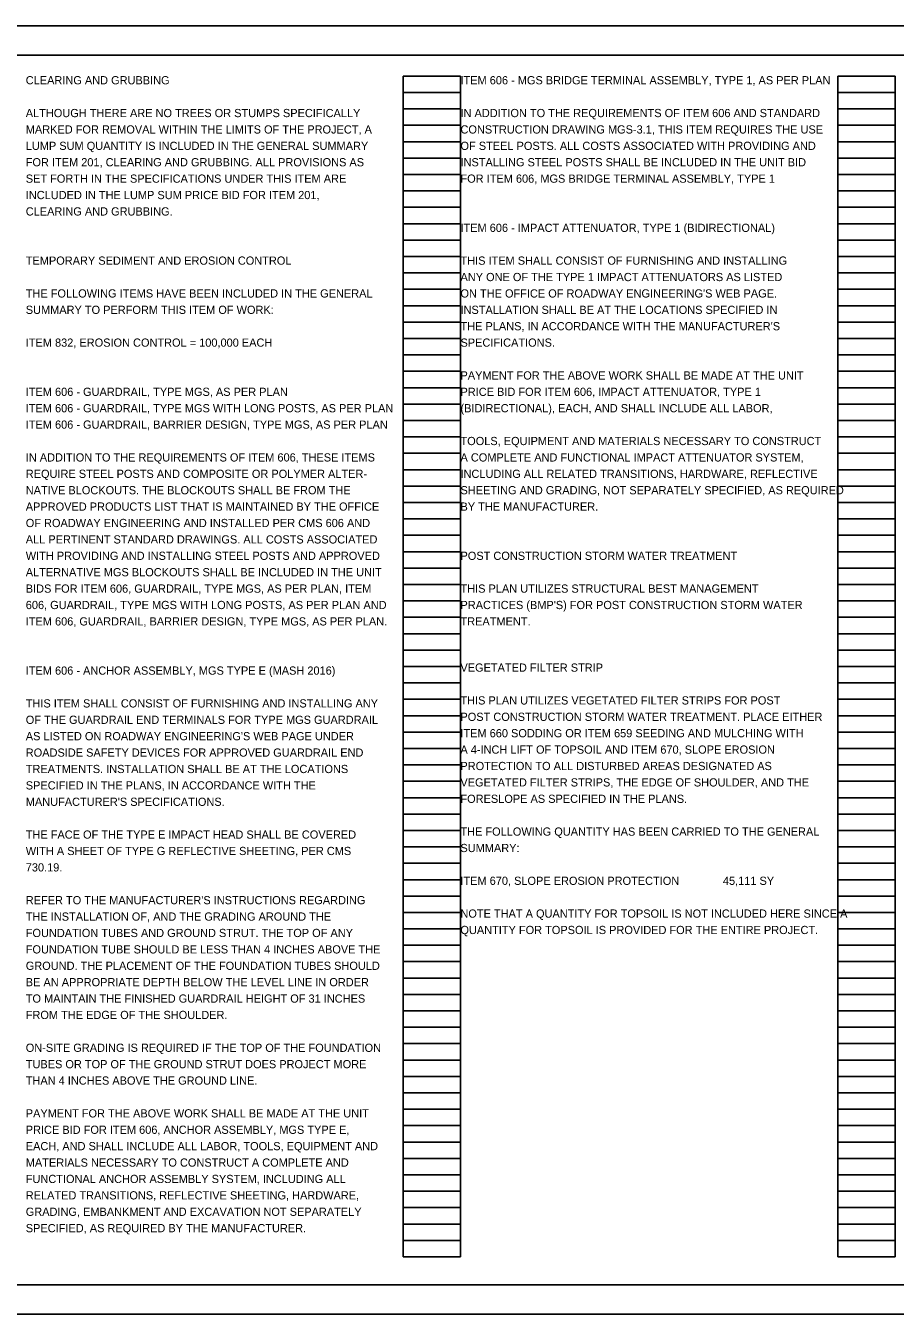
# Model space of a CAD drawing. Extents: x 0 to 46.1, y 0 to 22.
# Drawn here: x 9.82 to 24.66, y 0 to 22 of the extents above; entities that cross this region are included whole.
import ezdxf

# ---------------------------------------------------------------- set-up
doc = ezdxf.new("R2010")
doc.units = 0
for name, color, linetype in [('SH_Border', 7, 'Continuous'), ('SH_Cut_Line', 7, 'Continuous'), ('SH_Data', 7, 'Continuous'), ('SH_Text', 7, 'Continuous'), ('TX_P_Misc', 7, 'Continuous')]:
    doc.layers.add(name, color=color, linetype=linetype)

msp = doc.modelspace()

# ---------------------------------------------------------------- linework, layer by layer
at = {"layer": 'SH_Border'}
msp.add_lwpolyline([(1.5, 21.5), (33.5, 21.5), (33.5, 0.5), (1.5, 0.5)], close=True, dxfattribs=at)
at = {"layer": 'SH_Cut_Line'}
msp.add_lwpolyline([(0, 0), (34, 0), (34, 22), (0, 22)], close=True, dxfattribs=at)
at = {"layer": 'SH_Data'}
for p, q in [((16.26, 0.98), (16.26, 21.14)), ((16.26, 21.14), (17.24, 21.14)), ((17.24, 0.98), (17.24, 21.14)), ((23.68, 0.98), (23.68, 21.14)), ((23.68, 21.14), (24.66, 21.14)), ((24.66, 0.98), (24.66, 21.14)), ((16.26, 20.86), (17.24, 20.86)), ((23.68, 20.86), (24.66, 20.86)), ((16.26, 20.58), (17.24, 20.58)), ((23.68, 20.58), (24.66, 20.58)), ((16.26, 20.3), (17.24, 20.3)), ((23.68, 20.3), (24.66, 20.3)), ((16.26, 20.02), (17.24, 20.02)), ((23.68, 20.02), (24.66, 20.02)), ((16.26, 19.74), (17.24, 19.74)), ((23.68, 19.74), (24.66, 19.74)), ((16.26, 19.46), (17.24, 19.46)), ((23.68, 19.46), (24.66, 19.46)), ((16.26, 19.18), (17.24, 19.18)), ((23.68, 19.18), (24.66, 19.18)), ((16.26, 18.9), (17.24, 18.9)), ((23.68, 18.9), (24.66, 18.9)), ((16.26, 18.62), (17.24, 18.62)), ((23.68, 18.62), (24.66, 18.62)), ((16.26, 18.34), (17.24, 18.34)), ((23.68, 18.34), (24.66, 18.34)), ((16.26, 18.06), (17.24, 18.06)), ((23.68, 18.06), (24.66, 18.06)), ((16.26, 17.78), (17.24, 17.78)), ((23.68, 17.78), (24.66, 17.78)), ((16.26, 17.5), (17.24, 17.5)), ((23.68, 17.5), (24.66, 17.5)), ((16.26, 17.22), (17.24, 17.22)), ((23.68, 17.22), (24.66, 17.22)), ((16.26, 16.94), (17.24, 16.94)), ((23.68, 16.94), (24.66, 16.94)), ((16.26, 16.66), (17.24, 16.66)), ((23.68, 16.66), (24.66, 16.66)), ((16.26, 16.38), (17.24, 16.38)), ((23.68, 16.38), (24.66, 16.38)), ((16.26, 16.1), (17.24, 16.1)), ((23.68, 16.1), (24.66, 16.1)), ((16.26, 15.82), (17.24, 15.82)), ((23.68, 15.82), (24.66, 15.82)), ((16.26, 15.54), (17.24, 15.54)), ((23.68, 15.54), (24.66, 15.54)), ((16.26, 15.26), (17.24, 15.26)), ((23.68, 15.26), (24.66, 15.26)), ((16.26, 14.98), (17.24, 14.98)), ((23.68, 14.98), (24.66, 14.98)), ((16.26, 14.7), (17.24, 14.7)), ((23.68, 14.7), (24.66, 14.7)), ((16.26, 14.42), (17.24, 14.42)), ((23.68, 14.42), (24.66, 14.42)), ((16.26, 14.14), (17.24, 14.14)), ((23.68, 14.14), (24.66, 14.14)), ((16.26, 13.86), (17.24, 13.86)), ((23.68, 13.86), (24.66, 13.86)), ((16.26, 13.58), (17.24, 13.58)), ((23.68, 13.58), (24.66, 13.58)), ((16.26, 13.3), (17.24, 13.3)), ((23.68, 13.3), (24.66, 13.3)), ((16.26, 13.02), (17.24, 13.02)), ((23.68, 13.02), (24.66, 13.02)), ((16.26, 12.74), (17.24, 12.74)), ((23.68, 12.74), (24.66, 12.74)), ((16.26, 12.46), (17.24, 12.46)), ((23.68, 12.46), (24.66, 12.46)), ((16.26, 12.18), (17.24, 12.18)), ((23.68, 12.18), (24.66, 12.18)), ((16.26, 11.9), (17.24, 11.9)), ((23.68, 11.9), (24.66, 11.9)), ((16.26, 11.62), (17.24, 11.62)), ((23.68, 11.62), (24.66, 11.62)), ((16.26, 11.34), (17.24, 11.34)), ((23.68, 11.34), (24.66, 11.34)), ((16.26, 11.06), (17.24, 11.06)), ((23.68, 11.06), (24.66, 11.06)), ((16.26, 10.78), (17.24, 10.78)), ((23.68, 10.78), (24.66, 10.78)), ((16.26, 10.5), (17.24, 10.5)), ((23.68, 10.5), (24.66, 10.5)), ((16.26, 10.22), (17.24, 10.22)), ((23.68, 10.22), (24.66, 10.22)), ((16.26, 9.94), (17.24, 9.94)), ((23.68, 9.94), (24.66, 9.94)), ((16.26, 9.66), (17.24, 9.66)), ((23.68, 9.66), (24.66, 9.66)), ((16.26, 9.38), (17.24, 9.38)), ((23.68, 9.38), (24.66, 9.38)), ((16.26, 9.1), (17.24, 9.1)), ((23.68, 9.1), (24.66, 9.1)), ((16.26, 8.82), (17.24, 8.82)), ((23.68, 8.82), (24.66, 8.82)), ((16.26, 8.54), (17.24, 8.54)), ((23.68, 8.54), (24.66, 8.54)), ((16.26, 8.26), (17.24, 8.26)), ((23.68, 8.26), (24.66, 8.26)), ((16.26, 7.98), (17.24, 7.98)), ((23.68, 7.98), (24.66, 7.98)), ((16.26, 7.7), (17.24, 7.7)), ((23.68, 7.7), (24.66, 7.7)), ((16.26, 7.42), (17.24, 7.42)), ((23.68, 7.42), (24.66, 7.42)), ((16.26, 7.14), (17.24, 7.14)), ((23.68, 7.14), (24.66, 7.14)), ((16.26, 6.86), (17.24, 6.86)), ((23.68, 6.86), (24.66, 6.86)), ((16.26, 6.58), (17.24, 6.58)), ((23.68, 6.58), (24.66, 6.58)), ((16.26, 6.3), (17.24, 6.3)), ((23.68, 6.3), (24.66, 6.3)), ((16.26, 6.02), (17.24, 6.02)), ((23.68, 6.02), (24.66, 6.02)), ((16.26, 5.74), (17.24, 5.74)), ((23.68, 5.74), (24.66, 5.74)), ((16.26, 5.46), (17.24, 5.46)), ((23.68, 5.46), (24.66, 5.46)), ((16.26, 5.18), (17.24, 5.18)), ((23.68, 5.18), (24.66, 5.18)), ((16.26, 4.9), (17.24, 4.9)), ((23.68, 4.9), (24.66, 4.9)), ((16.26, 4.62), (17.24, 4.62)), ((23.68, 4.62), (24.66, 4.62)), ((16.26, 4.34), (17.24, 4.34)), ((23.68, 4.34), (24.66, 4.34)), ((16.26, 4.06), (17.24, 4.06)), ((23.68, 4.06), (24.66, 4.06)), ((16.26, 3.78), (17.24, 3.78)), ((23.68, 3.78), (24.66, 3.78)), ((16.26, 3.5), (17.24, 3.5)), ((23.68, 3.5), (24.66, 3.5)), ((16.26, 3.22), (17.24, 3.22)), ((23.68, 3.22), (24.66, 3.22)), ((16.26, 2.94), (17.24, 2.94)), ((23.68, 2.94), (24.66, 2.94)), ((16.26, 2.66), (17.24, 2.66)), ((23.68, 2.66), (24.66, 2.66)), ((16.26, 2.38), (17.24, 2.38)), ((23.68, 2.38), (24.66, 2.38)), ((16.26, 2.1), (17.24, 2.1)), ((23.68, 2.1), (24.66, 2.1)), ((16.26, 1.82), (17.24, 1.82)), ((23.68, 1.82), (24.66, 1.82)), ((16.26, 1.54), (17.24, 1.54)), ((23.68, 1.54), (24.66, 1.54)), ((16.26, 1.26), (17.24, 1.26)), ((23.68, 1.26), (24.66, 1.26)), ((16.26, 0.98), (17.24, 0.98)), ((23.68, 0.98), (24.66, 0.98))]:
    msp.add_line(p, q, dxfattribs=at)

# ---------------------------------------------------------------- texts
at = {"layer": 'SH_Text'}
for s, p in [('CLEARING AND GRUBBING', (9.82, 21)), ('ALTHOUGH THERE ARE NO TREES OR STUMPS SPECIFICALLY', (9.82, 20.44)), ('IN ADDITION TO THE REQUIREMENTS OF ITEM 606 AND STANDARD', (17.24, 20.44)), ('MARKED FOR REMOVAL WITHIN THE LIMITS OF THE PROJECT, A', (9.82, 20.16)), ('CONSTRUCTION DRAWING MGS-3.1, THIS ITEM REQUIRES THE USE', (17.24, 20.16)), ('LUMP SUM QUANTITY IS INCLUDED IN THE GENERAL SUMMARY', (9.82, 19.88)), ('OF STEEL POSTS. ALL COSTS ASSOCIATED WITH PROVIDING AND ', (17.24, 19.88)), ('FOR ITEM 201, CLEARING AND GRUBBING. ALL PROVISIONS AS', (9.82, 19.6)), ('INSTALLING STEEL POSTS SHALL BE INCLUDED IN THE UNIT BID ', (17.24, 19.6)), ('SET FORTH IN THE SPECIFICATIONS UNDER THIS ITEM ARE', (9.82, 19.32)), ('FOR ITEM 606, MGS BRIDGE TERMINAL ASSEMBLY, TYPE 1', (17.24, 19.32)), ('INCLUDED IN THE LUMP SUM PRICE BID FOR ITEM 201,', (9.82, 19.04)), ('CLEARING AND GRUBBING.', (9.82, 18.76)), ('ITEM 606 - IMPACT ATTENUATOR, TYPE 1 (BIDIRECTIONAL)', (17.24, 18.48)), ('TEMPORARY SEDIMENT AND EROSION CONTROL', (9.82, 17.92)), ('THIS ITEM SHALL CONSIST OF FURNISHING AND INSTALLING', (17.24, 17.92)), ('ANY ONE OF THE TYPE 1 IMPACT ATTENUATORS AS LISTED', (17.24, 17.64)), ('THE FOLLOWING ITEMS HAVE BEEN INCLUDED IN THE GENERAL', (9.82, 17.36)), ("ON THE OFFICE OF ROADWAY ENGINEERING'S WEB PAGE.", (17.24, 17.36)), ('SUMMARY TO PERFORM THIS ITEM OF WORK:', (9.82, 17.08)), ('INSTALLATION SHALL BE AT THE LOCATIONS SPECIFIED IN', (17.24, 17.08)), ("THE PLANS, IN ACCORDANCE WITH THE MANUFACTURER'S", (17.24, 16.8)), ('ITEM 832, EROSION CONTROL = 100,000 EACH', (9.82, 16.52)), ('SPECIFICATIONS.', (17.24, 16.52)), ('PAYMENT FOR THE ABOVE WORK SHALL BE MADE AT THE UNIT', (17.24, 15.96)), ('PRICE BID FOR ITEM 606, IMPACT ATTENUATOR, TYPE 1', (17.24, 15.68)), ('(BIDIRECTIONAL), EACH, AND SHALL INCLUDE ALL LABOR,', (17.24, 15.4)), ('TOOLS, EQUIPMENT AND MATERIALS NECESSARY TO CONSTRUCT ', (17.24, 14.84)), ('IN ADDITION TO THE REQUIREMENTS OF ITEM 606, THESE ITEMS ', (9.82, 14.56)), ('A COMPLETE AND FUNCTIONAL IMPACT ATTENUATOR SYSTEM, ', (17.24, 14.56)), ('REQUIRE STEEL POSTS AND COMPOSITE OR POLYMER ALTER- ', (9.82, 14.28)), ('INCLUDING ALL RELATED TRANSITIONS, HARDWARE, REFLECTIVE ', (17.24, 14.28)), ('NATIVE BLOCKOUTS. THE BLOCKOUTS SHALL BE FROM THE ', (9.82, 14)), ('SHEETING AND GRADING, NOT SEPARATELY SPECIFIED, AS REQUIRED ', (17.24, 14)), ('APPROVED PRODUCTS LIST THAT IS MAINTAINED BY THE OFFICE ', (9.82, 13.72)), ('BY THE MANUFACTURER.', (17.24, 13.72)), ('OF ROADWAY ENGINEERING AND INSTALLED PER CMS 606 AND ', (9.82, 13.44)), ('ALL PERTINENT STANDARD DRAWINGS. ALL COSTS ASSOCIATED ', (9.82, 13.16)), ('WITH PROVIDING AND INSTALLING STEEL POSTS AND APPROVED ', (9.82, 12.88)), ('POST CONSTRUCTION STORM WATER TREATMENT', (17.24, 12.88)), ('ALTERNATIVE MGS BLOCKOUTS SHALL BE INCLUDED IN THE UNIT ', (9.82, 12.6)), ('BIDS FOR ITEM 606, GUARDRAIL, TYPE MGS, AS PER PLAN, ITEM ', (9.82, 12.32)), ('THIS PLAN UTILIZES STRUCTURAL BEST MANAGEMENT', (17.24, 12.32)), ('606, GUARDRAIL, TYPE MGS WITH LONG POSTS, AS PER PLAN AND ', (9.82, 12.04)), ("PRACTICES (BMP'S) FOR POST CONSTRUCTION STORM WATER", (17.24, 12.04)), ('ITEM 606, GUARDRAIL, BARRIER DESIGN, TYPE MGS, AS PER PLAN.', (9.82, 11.76)), ('TREATMENT.', (17.24, 11.76)), ('ITEM 606 - ANCHOR ASSEMBLY, MGS TYPE E (MASH 2016)', (9.82, 10.92)), ('VEGETATED FILTER STRIP', (17.239, 10.971)), ('THIS ITEM SHALL CONSIST OF FURNISHING AND INSTALLING ANY', (9.82, 10.36)), ('THIS PLAN UTILIZES VEGETATED FILTER STRIPS FOR POST', (17.239, 10.411)), ('OF THE GUARDRAIL END TERMINALS FOR TYPE MGS GUARDRAIL', (9.82, 10.08)), ('POST CONSTRUCTION STORM WATER TREATMENT. PLACE EITHER', (17.239, 10.131)), ("AS LISTED ON ROADWAY ENGINEERING'S WEB PAGE UNDER", (9.82, 9.8)), ('ITEM 660 SODDING OR ITEM 659 SEEDING AND MULCHING WITH', (17.239, 9.851)), ('A 4-INCH LIFT OF TOPSOIL AND ITEM 670, SLOPE EROSION', (17.239, 9.571)), ('ROADSIDE SAFETY DEVICES FOR APPROVED GUARDRAIL END', (9.82, 9.52)), ('TREATMENTS. INSTALLATION SHALL BE AT THE LOCATIONS', (9.82, 9.24)), ('PROTECTION TO ALL DISTURBED AREAS DESIGNATED AS', (17.239, 9.291)), ('SPECIFIED IN THE PLANS, IN ACCORDANCE WITH THE', (9.82, 8.96)), ('VEGETATED FILTER STRIPS, THE EDGE OF SHOULDER, AND THE', (17.239, 9.011)), ("MANUFACTURER'S SPECIFICATIONS.", (9.82, 8.68)), ('FORESLOPE AS SPECIFIED IN THE PLANS.', (17.239, 8.731)), ('THE FACE OF THE TYPE E IMPACT HEAD SHALL BE COVERED', (9.82, 8.12)), ('THE FOLLOWING QUANTITY HAS BEEN CARRIED TO THE GENERAL ', (17.239, 8.171)), ('WITH A SHEET OF TYPE G REFLECTIVE SHEETING, PER CMS', (9.82, 7.84)), ('SUMMARY:', (17.239, 7.891)), ('730.19.', (9.82, 7.56)), ('ITEM 670, SLOPE EROSION PROTECTION', (17.239, 7.331)), ('45,111 SY', (21.719, 7.331)), ("REFER TO THE MANUFACTURER'S INSTRUCTIONS REGARDING", (9.82, 7)), ('THE INSTALLATION OF, AND THE GRADING AROUND THE', (9.82, 6.72)), ('NOTE THAT A QUANTITY FOR TOPSOIL IS NOT INCLUDED HERE SINCE A ', (17.239, 6.771)), ('QUANTITY FOR TOPSOIL IS PROVIDED FOR THE ENTIRE PROJECT.', (17.239, 6.491)), ('FOUNDATION TUBES AND GROUND STRUT. THE TOP OF ANY', (9.82, 6.44)), ('FOUNDATION TUBE SHOULD BE LESS THAN 4 INCHES ABOVE THE', (9.82, 6.16)), ('GROUND. THE PLACEMENT OF THE FOUNDATION TUBES SHOULD', (9.82, 5.88)), ('BE AN APPROPRIATE DEPTH BELOW THE LEVEL LINE IN ORDER', (9.82, 5.6)), ('TO MAINTAIN THE FINISHED GUARDRAIL HEIGHT OF 31 INCHES', (9.82, 5.32)), ('FROM THE EDGE OF THE SHOULDER.', (9.82, 5.04)), ('ON-SITE GRADING IS REQUIRED IF THE TOP OF THE FOUNDATION', (9.82, 4.48)), ('TUBES OR TOP OF THE GROUND STRUT DOES PROJECT MORE', (9.82, 4.2)), ('THAN 4 INCHES ABOVE THE GROUND LINE.', (9.82, 3.92)), ('PAYMENT FOR THE ABOVE WORK SHALL BE MADE AT THE UNIT', (9.82, 3.36)), ('PRICE BID FOR ITEM 606, ANCHOR ASSEMBLY, MGS TYPE E,', (9.82, 3.08)), ('EACH, AND SHALL INCLUDE ALL LABOR, TOOLS, EQUIPMENT AND', (9.82, 2.8)), ('MATERIALS NECESSARY TO CONSTRUCT A COMPLETE AND', (9.82, 2.52)), ('FUNCTIONAL ANCHOR ASSEMBLY SYSTEM, INCLUDING ALL', (9.82, 2.24)), ('RELATED TRANSITIONS, REFLECTIVE SHEETING, HARDWARE,', (9.82, 1.96)), ('GRADING, EMBANKMENT AND EXCAVATION NOT SEPARATELY', (9.82, 1.68)), ('SPECIFIED, AS REQUIRED BY THE MANUFACTURER.', (9.82, 1.4))]:
    msp.add_text(s, height=0.14, dxfattribs=at).set_placement(p)
at = {"layer": 'TX_P_Misc'}
for s, p in [('ITEM 606 - MGS BRIDGE TERMINAL ASSEMBLY, TYPE 1, AS PER PLAN', (17.24, 21)), ('ITEM 606 - GUARDRAIL, TYPE MGS, AS PER PLAN', (9.82, 15.68)), ('ITEM 606 - GUARDRAIL, TYPE MGS WITH LONG POSTS, AS PER PLAN', (9.82, 15.4)), ('ITEM 606 - GUARDRAIL, BARRIER DESIGN, TYPE MGS, AS PER PLAN', (9.82, 15.12))]:
    msp.add_text(s, height=0.14, dxfattribs=at).set_placement(p)

doc.saveas('drawing.dxf')
